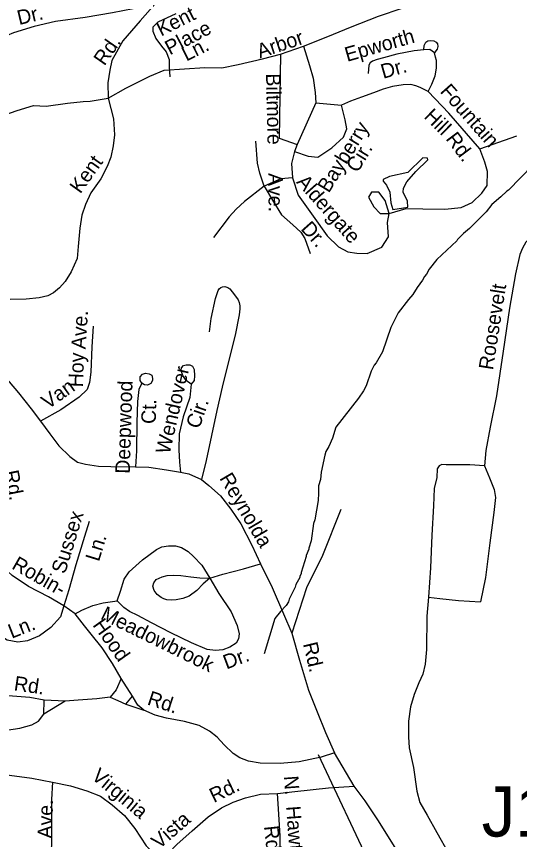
# Model space of a CAD drawing. Extents: x 1547597 to 1699558, y 810033 to 920809.
# Drawn here: x 1623759 to 1627044, y 859591 to 864963 of the extents above; entities that cross this region are included whole.
import ezdxf

# ---------------------------------------------------------------- set-up
doc = ezdxf.new("R2010")
doc.units = 0
for name, color, linetype in [('Exist Hydrographic Creek Single Shore', 7, 'Continuous'), ('Exist Hydrographic Misc Water Feature', 7, 'Continuous'), ('Exist Road Non-System Structure Non-Sys Other Number Label', 7, 'Continuous'), ('Exist Road Non-System Type 51', 7, 'Continuous'), ('Exist Road Non-System Type 51 Label', 7, 'Continuous')]:
    doc.layers.add(name, color=color, linetype=linetype)

msp = doc.modelspace()

# ---------------------------------------------------------------- linework, layer by layer
at = {"layer": 'Exist Hydrographic Creek Single Shore'}
msp.add_lwpolyline([(1627327.5, 858118.6), (1626992.9, 858301.6), (1626794.9, 858440.7), (1626787.8, 858499.9), (1626689.8, 858675.8), (1626253.8, 859131.2), (1626081.8, 859400.6), (1625731.7, 860143.7)], dxfattribs=at)
at = {"layer": 'Exist Hydrographic Misc Water Feature'}
for points in [[(1626203.5, 863746.8), (1626216, 863703.1), (1626314, 863719.6), (1626312.2, 863758.6), (1626284.5, 863817.1), (1626287, 863843.1), (1626307.4, 863884.1), (1626366.2, 863950.8), (1626444.3, 864028), (1626443.6, 864037.9), (1626411.6, 864040.6), (1626314.2, 863944.5), (1626195.4, 863919.1), (1626152.3, 863898.2), (1626152.2, 863887.4), (1626175.6, 863861.2), (1626196.5, 863815.7), (1626203.5, 863746.8)], [(1627130.5, 863992.5), (1626970.4, 863828.8), (1626960.3, 863822.9), (1626921.8, 863785.4), (1626863.1, 863736.3), (1626824.6, 863688.8), (1626779.9, 863641.4), (1626717.1, 863580.3), (1626676.6, 863546.9), (1626638.2, 863507.4), (1626634.1, 863499.5), (1626504.5, 863377.3), (1626453.6, 863314.1), (1626437.2, 863282.3), (1626423, 863266.5), (1626410.7, 863242.7), (1626376, 863195.1), (1626347.4, 863147.6), (1626319, 863116), (1626251.9, 863028.9), (1626202.6, 862933.7), (1626148.4, 862774.5), (1626107.5, 862703), (1626095.2, 862687.2), (1626074.7, 862647.6), (1626041.5, 862552), (1626025, 862520.2), (1625992.4, 862472.7), (1625843.9, 862282.9), (1625822.9, 862211.1), (1625798.2, 862155.5), (1625779.7, 862123.7), (1625773.4, 862099.9), (1625747.9, 861988.2), (1625743.2, 861940.3), (1625730.7, 861900.4), (1625732.1, 861852.5), (1625729.4, 861804.6), (1625707.7, 861676.8), (1625699.4, 861652.9), (1625683.8, 861541.2), (1625667.2, 861493.5), (1625667.1, 861485.5), (1625650.6, 861445.7), (1625650.5, 861437.7), (1625617, 861334.2), (1625616.9, 861326.2), (1625608.7, 861310.3), (1625608.6, 861302.3), (1625583.9, 861254.7), (1625579.7, 861238.7), (1625538.7, 861159.4), (1625534.5, 861143.4), (1625520.1, 861119.6), (1625483.6, 861080.1), (1625447, 861032.7), (1625375.8, 860803.5)]]:
    msp.add_lwpolyline(points, dxfattribs=at)
at = {"layer": 'Exist Road Non-System Type 51'}
for p, q in [((1624800.5, 864979.4), (1624682.9, 864926.5)), ((1624682.9, 864926.5), (1624650.6, 864894.1)), ((1624650.6, 864894.1), (1624650.6, 864867.6)), ((1624650.6, 864867.6), (1624668.2, 864820.5)), ((1624668.2, 864820.5), (1624706.4, 864770.5)), ((1624706.4, 864770.5), (1624735.8, 864732.3)), ((1625484, 864717.6), (1625632.2, 864768.7)), ((1624735.8, 864732.3), (1624756.4, 864682.3)), ((1624756.4, 864682.3), (1624756.4, 864635.2)), ((1624756.4, 864635.2), (1624759.6, 864569.3)), ((1624142.8, 861064.9), (1624069.6, 861116)), ((1624517.5, 860527), (1624443.4, 860642.2)), ((1623938.8, 860409.3), (1623940.3, 860501.3)), ((1624078, 860494.9), (1623938.8, 860409.3)), ((1624078, 860494.9), (1623940.3, 860501.3)), ((1624473.4, 860474.5), (1624517.5, 860527)), ((1624473.4, 860474.5), (1624589.9, 860435.9)), ((1625963.6, 859939.1), (1625835.7, 860157.8))]:
    msp.add_line(p, q, dxfattribs=at)
for points in [[(1625632.2, 864768.7), (1625792.6, 864831.9), (1625940.9, 864892.8), (1626123.2, 864965.7), (1626276.3, 865017.2), (1626435.7, 865087.1)], [(1624620.7, 865036.2), (1624520.4, 865013.8), (1624387.1, 864988), (1624207, 864957), (1624014.7, 864930.1), (1623874.3, 864898), (1623740.6, 864856.7), (1623658, 864822.6), (1623538.4, 864758.4)], [(1624664.2, 865046.4), (1624567, 864934.5), (1624452.9, 864803.2), (1624382.4, 864674.8), (1624369.4, 864613), (1624355.7, 864530.8), (1624358.4, 864430)], [(1626417.7, 864745), (1626420.2, 864773), (1626432.5, 864794.7), (1626445.1, 864804.1), (1626462.3, 864807.1), (1626484.5, 864803.9), (1626498.9, 864796.4), (1626508.5, 864783.6), (1626509.2, 864767.2), (1626505.2, 864750.2), (1626497.4, 864739.2), (1626487.3, 864726)], [(1625632.2, 864768.7), (1625671.3, 864643), (1625695.6, 864560.3), (1625710.2, 864467.9), (1625712.6, 864399.8)], [(1626417.7, 864745), (1626355.7, 864738.1), (1626241.4, 864718), (1626155.1, 864693.3), (1626113, 864682.1), (1626082.8, 864670.5), (1626067.6, 864660.5), (1626060.4, 864645), (1626055.5, 864591.1)], [(1626487.3, 864726), (1626457.7, 864748.4), (1626417.7, 864745)], [(1624358.4, 864430), (1624473.6, 864494.7), (1624630.3, 864574.5), (1624722.6, 864613.5), (1624856.3, 864620.8), (1624988.2, 864629.3), (1625100, 864627.4), (1625206.3, 864649.9), (1625366, 864686.1), (1625484, 864717.6)], [(1625484, 864717.6), (1625474.5, 864168.7), (1625591.1, 864127.4)], [(1626447.2, 864472.6), (1626469.9, 864520.4), (1626492.9, 864576), (1626501.7, 864625.8), (1626502.5, 864675.6), (1626494.7, 864697.8), (1626487.3, 864726)], [(1626447.2, 864472.6), (1626395.7, 864499.5), (1626366.9, 864511.5), (1626334, 864518.6), (1626284, 864517), (1626213.9, 864506.6), (1626153.7, 864489.4), (1626089.4, 864464.5), (1626011, 864435.9), (1625940.6, 864411.1), (1625882.3, 864384.1)], [(1626783.6, 864099), (1626581.9, 864331.8), (1626447.2, 864472.6)], [(1623675.8, 864320), (1623764.2, 864348.6), (1623870.6, 864382.9), (1623952.5, 864377.4), (1624093.2, 864397), (1624195.3, 864409.2), (1624239.5, 864411), (1624358.4, 864430)], [(1624358.4, 864430), (1624392.1, 864294.8), (1624399.5, 864190.3), (1624390.2, 864118.5), (1624376.4, 864044.7), (1624351.4, 863983.2), (1624310.1, 863903.9), (1624244.8, 863812.9), (1624209.4, 863735.6), (1624186.4, 863666), (1624172.9, 863582.3), (1624163, 863462.6), (1624155.6, 863382.7), (1624116.3, 863297.5), (1624077.4, 863234), (1624040.7, 863192.7), (1624000.2, 863159.3), (1623963.8, 863139.9), (1623907.7, 863126.8), (1623823.7, 863118.3), (1623717.8, 863116)], [(1625574.1, 864081.2), (1625664, 864052), (1625727.2, 864044.7), (1625817.1, 864105.5), (1625894.9, 864176), (1625916.8, 864229.5), (1625904.6, 864287.9), (1625882.3, 864384.1)], [(1625712.6, 864399.8), (1625591.1, 864127.4)], [(1625712.6, 864399.8), (1625882.3, 864384.1)], [(1625377.2, 863855.3), (1625348.1, 863940.4), (1625333.5, 864006.1), (1625321.3, 864149.6)], [(1626783.6, 864099), (1627026.7, 864183.4)], [(1625591.1, 864127.4), (1625574.1, 864081.2)], [(1626191.5, 863678.3), (1626303.2, 863710), (1626412.6, 863707.5), (1626556, 863705.1), (1626662.9, 863717.2), (1626735, 863748.7), (1626798.2, 863809.5), (1626832.2, 863860.6), (1626834.7, 863950.6), (1626817.7, 864011.4), (1626783.6, 864099)], [(1625574.1, 864081.2), (1625554.7, 864004.3), (1625562, 863909.4)], [(1625562, 863909.4), (1625484.2, 863903.9), (1625377.2, 863855.3)], [(1625562, 863909.4), (1625598.4, 863797.5), (1625695.7, 863658.9), (1625788, 863532.4), (1625860.9, 863459.4), (1625921.7, 863427.8), (1625982.4, 863418.1), (1626048.1, 863415.6), (1626145.3, 863457), (1626189, 863525.1), (1626181.7, 863617.5), (1626191.5, 863678.3)], [(1625377.2, 863855.3), (1625248.3, 863756.6), (1625192.5, 863705.5), (1625148.7, 863654.5), (1625046.6, 863520.7)], [(1625377.2, 863855.3), (1625430.6, 863763.9), (1625489, 863669.1), (1625564.3, 863603.4), (1625615.3, 863554.7), (1625642.1, 863513.4), (1625676.1, 863416.1)], [(1626191.5, 863678.3), (1626167.1, 863761), (1626125.8, 863817), (1626077.2, 863817), (1626057.8, 863782.9), (1626091.8, 863719.7), (1626133.1, 863678.3), (1626181.7, 863678.3), (1626191.5, 863678.3)], [(1627372.6, 863643.6), (1627304.5, 863626.6), (1627208, 863588.3), (1627135.3, 863543.4), (1627084.4, 863490.4), (1627061.8, 863450.6), (1627045.1, 863408.9), (1627017.1, 863283.6), (1626977.4, 863058.3), (1626936.9, 862779.2), (1626892.1, 862487.9), (1626850.8, 862282.8), (1626824.2, 862129.3), (1626814.6, 862029.4)], [(1625018.8, 862904.9), (1625030.2, 862992.6), (1625058.2, 863122.1), (1625077.1, 863175.7), (1625083.5, 863185.4), (1625093.5, 863193.6), (1625105.4, 863198.9), (1625119.5, 863201.1), (1625139.3, 863194.9), (1625153.3, 863184.6), (1625182.6, 863146.2), (1625205.9, 863113.7), (1625213.4, 863096.7), (1625217.4, 863075.6), (1625217.7, 863055), (1625212.3, 863015.7), (1625186.3, 862884.1), (1625143.3, 862710.9), (1625102.7, 862543.6), (1625068.2, 862392.3), (1624998.8, 862065.7), (1624966.2, 861940.9)], [(1624260.3, 862941.1), (1624252, 862807.4), (1624245.2, 862641.7), (1624236.1, 862573.8), (1624221.3, 862528.1), (1624168.7, 862478.9), (1624049.3, 862394.9), (1623916.3, 862322.3)], [(1623611.9, 862694.2), (1623773, 862506.4), (1623855.1, 862403.1), (1623916.3, 862322.3)], [(1624899.2, 862563), (1624867.7, 862587.4), (1624846.1, 862620.9), (1624834.8, 862651.9), (1624837.2, 862670.7), (1624850.4, 862684.6), (1624867.3, 862689.5), (1624891.3, 862689), (1624909.2, 862680.8), (1624918.8, 862658.6), (1624922.1, 862618.5), (1624919.5, 862586.6), (1624899.2, 862563)], [(1624577.8, 862570.3), (1624565.9, 862586.3), (1624566.4, 862611.4), (1624581, 862628.1), (1624600.7, 862635.9), (1624624.6, 862631.4), (1624642.4, 862621.2), (1624648, 862601.1), (1624648, 862587.1), (1624636.6, 862567.5), (1624615.1, 862557.7), (1624595.7, 862558.1), (1624577.8, 862570.3)], [(1624577.8, 862570.3), (1624557.1, 862528.5), (1624549.7, 862450.8), (1624545.5, 862312.8), (1624542.4, 862129), (1624536.1, 862023.8)], [(1624899.2, 862563), (1624891.9, 862477.1), (1624847.7, 862349.9), (1624822, 862238.4), (1624820.3, 862134.5), (1624822.8, 862054.4), (1624829.1, 861989.1)], [(1623916.3, 862322.3), (1623976.1, 862240), (1624036.5, 862160.5), (1624108.2, 862090.7), (1624156.8, 862055.2), (1624211, 862040.2), (1624295, 862027.1), (1624376.2, 862026.5), (1624536.1, 862023.8)], [(1624536.1, 862023.8), (1624623.9, 862022.5), (1624739.6, 862004.5), (1624829.1, 861989.1)], [(1626814.6, 862029.4), (1626718.9, 862037), (1626565, 862037.5), (1626537, 862038.1), (1626518.9, 862030.4), (1626506.7, 862010.5), (1626503.7, 861954.7), (1626486.5, 861883), (1626482.7, 861769), (1626471.5, 861577.3), (1626461.9, 861363.6), (1626448.8, 861172)], [(1626814.6, 862029.4), (1626847.2, 861951.1), (1626877.9, 861876.7), (1626887.1, 861824.5), (1626875.5, 861724.6), (1626850.2, 861527.2), (1626820.7, 861301.9), (1626788, 861142.5)], [(1624829.1, 861989.1), (1624884.9, 861978.1), (1624966.2, 861940.9)], [(1624966.2, 861940.9), (1625015.5, 861902.1), (1625090.3, 861834.9), (1625158.8, 861747.9), (1625223.1, 861650.9), (1625296.7, 861511.7), (1625352.7, 861390.9)], [(1625875.8, 861744.2), (1625757.9, 861446), (1625653, 861233.9), (1625557, 860937.9)], [(1624233.9, 861666.2), (1624204.3, 861568.7), (1624147.3, 861383.8), (1624100.8, 861220.6), (1624069.6, 861116)], [(1624069.6, 861116), (1623968.8, 861175.7), (1623838, 861241.8), (1623731.3, 861315.4), (1623587.6, 861445.6), (1623444.3, 861614.7)], [(1624417.1, 861149.6), (1624438.2, 861213.2), (1624463.4, 861290.7), (1624494.1, 861338.1), (1624581.4, 861416.8), (1624674.4, 861483.1), (1624708.6, 861500.7), (1624752.7, 861507.8), (1624796.6, 861509.1), (1624836.3, 861496.5), (1624880.1, 861471.8), (1624915.4, 861439.2), (1624968.5, 861382.3), (1625021, 861297.6)], [(1625021, 861297.6), (1625107.4, 861322.3), (1625241.7, 861358), (1625352.7, 861390.9)], [(1625352.7, 861390.9), (1625428, 861235.7), (1625503.1, 861064.7), (1625557, 860937.9)], [(1625021, 861297.6), (1624978.2, 861260), (1624935.9, 861216.3), (1624887.1, 861179.9), (1624846.4, 861164.9), (1624800.8, 861155.2), (1624770.7, 861153), (1624742, 861155.2), (1624721.1, 861161), (1624703.3, 861170.8), (1624677.7, 861191.3), (1624657.9, 861215.5), (1624650.5, 861243.7), (1624655.8, 861267.2), (1624671.2, 861287.3), (1624709.4, 861306.7), (1624743.4, 861314.6), (1624781.5, 861317.5), (1624833.4, 861314.6), (1624897.3, 861305.5), (1624957, 861298.7), (1625021, 861297.6)], [(1624069.6, 861116), (1624047.2, 861045.2), (1623984.1, 860974.2), (1623909.3, 860919.5), (1623830.9, 860888.7), (1623768.9, 860879.8), (1623699.1, 860893), (1623626.2, 860935.4), (1623546.9, 860972.7), (1623488.7, 861029), (1623414.7, 861097.5), (1623363.7, 861158.1), (1623312.5, 861199), (1623249.1, 861230.1), (1623197.4, 861247), (1623123.7, 861254.1), (1623054, 861269.3)], [(1625021, 861297.6), (1625081.2, 861196.7), (1625161.2, 861077.4), (1625199.6, 860988.8), (1625212.8, 860934.7), (1625208.3, 860900.8), (1625193.7, 860873.1), (1625153.3, 860845.7), (1625107.1, 860828.4), (1625059, 860823.8), (1625005.3, 860830.7), (1624902.1, 860873.8), (1624767.4, 860939.9), (1624640.5, 861006), (1624551.4, 861053.4), (1624497.9, 861080.3), (1624460.4, 861104.9), (1624417.1, 861149.6)], [(1624142.8, 861064.9), (1624186.3, 861087.2), (1624258.8, 861118.2), (1624325, 861137), (1624417.1, 861149.6)], [(1626448.8, 861172), (1626438.9, 861048.1), (1626435.3, 860832.3), (1626427.8, 860736.6), (1626412.6, 860670.8), (1626385.7, 860613.3), (1626356.5, 860537.9), (1626331.3, 860458.2), (1626317.6, 860364.6), (1626317.9, 860260.5), (1626322.8, 860188.6), (1626350.7, 860062.2), (1626374.1, 859905.8), (1626392.9, 859833.6), (1626439.4, 859749), (1626503.5, 859637.8), (1626579.2, 859502.8), (1626634, 859427.9)], [(1626448.8, 861172), (1626522.7, 861164.7), (1626644.3, 861150.8), (1626788, 861142.5)], [(1624443.4, 860642.2), (1624387.2, 860740.9), (1624318.8, 860842.2), (1624246.4, 860931.3), (1624203.4, 860985.8), (1624142.8, 861064.9)], [(1625557, 860937.9), (1625606, 860761.2), (1625666.7, 860566.3), (1625722.3, 860425.5), (1625776, 860288.7), (1625835.7, 860157.8)], [(1623940.3, 860501.3), (1623846.8, 860518.8), (1623733.1, 860526.5), (1623649.1, 860532), (1623579.9, 860569), (1623504.8, 860626.2), (1623472.3, 860644.8), (1623427.5, 860661.4), (1623333.9, 860674.9)], [(1624443.4, 860642.2), (1624411.1, 860567.6), (1624370.3, 860520.2)], [(1624370.3, 860520.2), (1624284.2, 860509.5), (1624162.2, 860499.6), (1624078, 860494.9)], [(1624370.3, 860520.2), (1624421.7, 860497.9), (1624473.4, 860474.5)], [(1624589.9, 860435.9), (1624552.3, 860468.4), (1624517.5, 860527)], [(1623509.6, 860312.3), (1623595.6, 860307), (1623693.4, 860305.4), (1623781.5, 860317.8), (1623859.7, 860338.6), (1623904.1, 860363.9), (1623938.8, 860409.3)], [(1625835.7, 860157.8), (1625749.5, 860129.2), (1625605, 860097.5), (1625481.3, 860087.2), (1625349.3, 860089.7), (1625273.5, 860103), (1625217.9, 860124), (1625174.5, 860152.7), (1625115.4, 860209.5), (1625070.4, 860258.2), (1625019.2, 860299.1), (1624951.7, 860336.1), (1624856.3, 860361.6), (1624738.7, 860383.6), (1624665.3, 860402.7), (1624589.9, 860435.9)], [(1623508.9, 860022.6), (1623646.8, 860020.2), (1623860.1, 859990.8), (1623995.4, 859964.7)], [(1623995.4, 859964.7), (1623987.6, 859852.8), (1623987, 859567), (1623983.9, 859476.9)], [(1623995.4, 859964.7), (1624113, 859940.7), (1624218.2, 859908.9), (1624307.5, 859873.5), (1624384.7, 859818.3), (1624463.5, 859747), (1624532, 859664), (1624606, 859550.8), (1624639.5, 859516.3)], [(1625462.7, 859890.7), (1625576.9, 859905), (1625797.1, 859929.3), (1625963.6, 859939.1)], [(1626441.5, 859231.6), (1626361.3, 859344.9), (1626230.8, 859538.9), (1626117.8, 859718.7), (1626035.9, 859844), (1625963.6, 859939.1)], [(1624753.1, 859504.4), (1624806, 859559.6), (1624907.3, 859648), (1625010.8, 859738.1), (1625097.7, 859798.8), (1625174, 859835.5), (1625254.5, 859864.1), (1625352.8, 859886.5), (1625462.7, 859890.7)], [(1625495.6, 859340.5), (1625483.4, 859450.6), (1625480.1, 859612.6), (1625472.6, 859756.6), (1625462.7, 859890.7)]]:
    msp.add_lwpolyline(points, dxfattribs=at)

# ---------------------------------------------------------------- texts
at = {"layer": 'Exist Road Non-System Structure Non-Sys Other Number Label'}
msp.add_text('J172', height=328.08, dxfattribs=at).set_placement((1626796.4, 859610.1))
at = {"layer": 'Exist Road Non-System Type 51 Label'}
for s, rotation, p in [('Dr.', 13.3072, (1623776.2, 864907.2)), ('Kent', 26.5408, (1624702.9, 864831.3)), ('Place', 28.0148, (1624760.7, 864708.9)), ('Arbor', 18.598, (1625347.8, 864688.3)), ('Epworth', 15.9405, (1625918.1, 864666.6)), ('Rd.', 55.1734, (1624333.6, 864636.3)), ('Ln.', 26.7205, (1624868.6, 864668.3)), ('Dr.', 15.9405, (1626153.4, 864555.7)), ('Biltmore', 271.2632, (1625388.2, 864590.8)), ('Fountain', 311.454, (1626519.8, 864471.5)), ('Hill', 315.4075, (1626413.9, 864304.6)), ('Bayberry', 58.3997, (1625798.3, 863806.4)), ('Rd.', 306.8893, (1626558, 864164.1)), ('Cir.', 58.3997, (1625985.5, 863937.8)), ('Kent', 54.3239, (1624175.9, 863801.3)), ('Ave.', 270.5508, (1625403.2, 863941.1)), ('Aldergate', 311.542, (1625581.9, 863879.7)), ('Dr.', 311.542, (1625611, 863574.7)), ('Roosevelt', 81.0984, (1626869.7, 862651.7)), ('Ave.', 86.442, (1624210.9, 862789.2)), ('Hoy', 87.6628, (1624192.7, 862541.6)), ('Wendover', 77.0365, (1624758.7, 862102.2)), ('Van', 35.1428, (1623964.6, 862396.6)), ('Deepwood', 88.2569, (1624498.8, 861977.5)), ('Ct.', 88.2569, (1624668.2, 862302.4)), ('Cir.', 70.8339, (1624952.3, 862266.2)), ('Rd.', 281.19, (1623678.2, 861992.6)), ('Reynolda', 300.5296, (1625081.6, 861949.6)), ('Sussex', 72.8761, (1624076.1, 861319.8)), ('Ln.', 72.8761, (1624297.3, 861400.7)), ('Robin-', 330.2235, (1623722.2, 861362.2)), ('Meadowbrook', 333.8432, (1624302.2, 861033.2)), ('Hood', 305.3361, (1624253.1, 860990.8)), ('Ln.', 21.4457, (1623727.8, 860901.1)), ('Rd.', 283.4109, (1625629.3, 860867.9)), ('Dr.', 20.5056, (1625129.9, 860700.6)), ('Rd.', 351.7838, (1623738.9, 860565.4)), ('Rd.', 341.916, (1624607.7, 860473.5)), ('Virginia', 320.0196, (1624242.8, 859992.8)), ('Rd.', 25.6443, (1625047.5, 859829.3)), ('N.  Hawthorne', 274.2167, (1625504.5, 860004.5)), ('Ave.', 88.759, (1623991.8, 859597.2)), ('Vista', 41.1244, (1624691, 859524.4)), ('Rd.', 276.3081, (1625374.7, 859677.2))]:
    msp.add_text(s, height=95, rotation=rotation, dxfattribs=at).set_placement(p)

doc.saveas('drawing.dxf')
